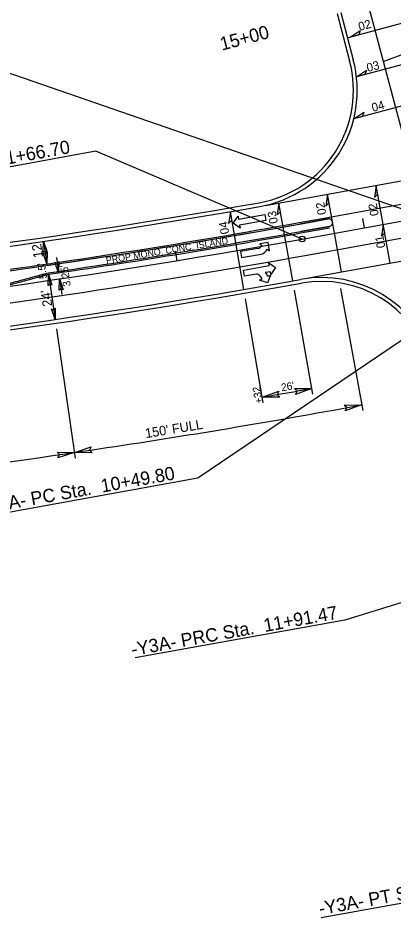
# Model space of a CAD drawing. Extents: x 1616561 to 1622460, y 896726 to 899651.
# Drawn here: x 1620740.5 to 1620937.7, y 897748.5 to 898221.3 of the extents above; entities that cross this region are included whole.
import ezdxf

# ---------------------------------------------------------------- set-up
doc = ezdxf.new("R2010")
doc.units = 0
for name, color, linetype in [('Exist Boundary Study Area', 7, 'Continuous'), ('Old_Level_3', 7, 'Continuous'), ('Prop Dimension', 7, 'Continuous'), ('Prop Horizontal Alignment Tick Small', 7, 'Continuous'), ('Prop Lane Arrow CELL', 7, 'Continuous'), ('Prop North Arrow NAD83 for Plan Sheets CELL', 7, 'Continuous'), ('Prop Shade Medium', 7, 'Continuous'), ('Prop Superelevation  Arrow CELL', 7, 'Continuous'), ('Prop Terminator CELL', 7, 'Continuous'), ('Sheet Cutting Line CELL', 7, 'Continuous'), ('Sheet North Arrow CELL', 7, 'Continuous'), ('Sheet Sticker Preliminary CELL', 7, 'Continuous')]:
    doc.layers.add(name, color=color, linetype=linetype)

msp = doc.modelspace()

# ---------------------------------------------------------------- linework, layer by layer
at = {"layer": 'Exist Boundary Study Area'}
for p, q in [((1620888.43, 898113.07), (1620903.49, 898115.8)), ((1620904.21, 898111.86), (1620889.15, 898109.14))]:
    msp.add_line(p, q, dxfattribs=at)
for centre, radius, start, end in [((1620903.85, 898113.83), 2, 280.2599, 100.2599), ((1620177.4, 902041.24), 3992, 277.72898, 280.25995), ((1620177.4, 902041.24), 3992, 278.41537, 280.25995), ((1620177.4, 902041.24), 3996, 278.33058, 280.25995), ((1620177.4, 902041.24), 3992, 278.33302, 278.41537)]:
    msp.add_arc(centre, radius, start, end, dxfattribs=at)
msp.add_open_spline([(1620715.49, 898076.55), (1620716.92, 898076.93), (1620722.41, 898078.36), (1620731.96, 898080.87), (1620742.09, 898083.56), (1620749.18, 898085.47), (1620752.22, 898086.29), (1620753.74, 898086.7), (1620754.25, 898086.84), (1620755.26, 898087.11), (1620755.77, 898087.25), (1620756.36, 898087.4)], degree=3, dxfattribs=at)
at = {"layer": 'Old_Level_3'}
for p, q in [((1620903.36, 898116.54), (1621261.54, 898181.37)), ((1620870.63, 898122.84), (1621020.48, 898149.94)), ((1620891.42, 898096.59), (1621018.65, 898119.62)), ((1620888.3, 898113.81), (1620903.36, 898116.54)), ((1620889.28, 898108.4), (1620904.34, 898111.13)), ((1620893.24, 898084.73), (1621042.18, 898111.69))]:
    msp.add_line(p, q, dxfattribs=at)
for radius, start in [(3991.25, 277.72898), (3996.75, 278.33058), (4008.75, 276.89819)]:
    msp.add_arc((1620177.4, 902041.24), radius, start, 280.25995, dxfattribs=at)
msp.add_open_spline([(1620715.59, 898075.81), (1620722.49, 898077.6), (1620729.29, 898079.39), (1620739.49, 898082.09), (1620742.88, 898083), (1620747.13, 898084.14), (1620747.98, 898084.37), (1620749.68, 898084.83), (1620750.53, 898085.06), (1620751.8, 898085.4), (1620752.44, 898085.57), (1620753.07, 898085.74), (1620753.5, 898085.86), (1620753.71, 898085.91), (1620754.35, 898086.09), (1620754.77, 898086.2), (1620755.62, 898086.43), (1620756.04, 898086.55), (1620756.47, 898086.66)], degree=3, dxfattribs=at)
at = {"layer": 'Prop Dimension'}
for p, q in [((1620753.93, 898103.98), (1620755.67, 898092.1)), ((1620760.65, 898095.41), (1620761.81, 898087.45)), ((1620756.47, 898086.66), (1620759.94, 898062.92)), ((1620762.28, 898084.23), (1620763.48, 898076.07)), ((1620910.11, 898079.25), (1620921.73, 898015.08)), ((1620910.11, 898079.25), (1620915.82, 898047.69)), ((1620760.67, 898057.97), (1620770.61, 897990.09)), ((1620906.32, 898015.34), (1620921.19, 898018.03))]:
    msp.add_line(p, q, dxfattribs=at)
for start, end in [(278.33169, 280.25995), (276.90211, 278.33169)]:
    msp.add_arc((1620176.16, 902049.2), 4099.41, start, end, dxfattribs=at)
at = {"layer": 'Prop Horizontal Alignment Tick Small'}
msp.add_line((1620908.26, 898223.61), (1620914.86, 898198.77), dxfattribs=at)
for centre, radius, start, end in [((1620856.87, 898183.37), 60, 279.9888, 14.8727), ((1620177.4, 902041.24), 3977.25, 270, 279.98877), ((1620177.4, 902041.24), 4022.75, 270, 280.19565), ((1620900.09, 898022.96), 60, 17.4099, 100.1956)]:
    msp.add_arc(centre, radius, start, end, dxfattribs=at)
at = {"layer": 'Prop Lane Arrow CELL'}
for p, q in [((1620853.63, 898113.48), (1620856.18, 898117.18)), ((1620856.18, 898117.18), (1620856.44, 898115.7)), ((1620856.44, 898115.7), (1620870.22, 898118.12)), ((1620870.79, 898114.87), (1620857.01, 898112.45)), ((1620870.22, 898118.12), (1620870.79, 898114.87)), ((1620857.27, 898110.98), (1620853.63, 898113.48)), ((1620857.01, 898112.45), (1620857.27, 898110.98)), ((1620872.03, 898103.34), (1620867.59, 898102.64)), ((1620867.59, 898102.64), (1620868.8, 898101.78)), ((1620872.72, 898099), (1620872.03, 898103.34)), ((1620866.53, 898100.22), (1620857.51, 898098.68)), ((1620857.51, 898098.68), (1620858.06, 898095.43)), ((1620858.06, 898095.43), (1620868.46, 898097.21)), ((1620871.51, 898099.86), (1620872.72, 898099)), ((1620859.03, 898088.87), (1620872.62, 898091.26)), ((1620872.62, 898091.26), (1620872.36, 898092.74)), ((1620872.36, 898092.74), (1620875.96, 898090.17)), ((1620859.6, 898085.62), (1620859.03, 898088.87)), ((1620865.95, 898086.74), (1620859.6, 898085.62)), ((1620873.19, 898088.01), (1620870.38, 898087.52)), ((1620873.19, 898086.28), (1620871.69, 898082.11)), ((1620871.83, 898085.64), (1620873.19, 898086.28)), ((1620873.45, 898086.53), (1620873.19, 898088.01)), ((1620875.96, 898090.17), (1620873.45, 898086.53)), ((1620867.52, 898083.61), (1620868.83, 898084.25)), ((1620871.69, 898082.11), (1620867.52, 898083.61))]:
    msp.add_line(p, q, dxfattribs=at)
for centre, radius, start, end in [((1620865.99, 898103.44), 3.27, 279.6782, 329.3364), ((1620866.81, 898102.17), 5.25, 288.3543, 333.666), ((1620865.74, 898084.22), 2.52, 49.0321, 85.3441), ((1620867.7, 898084), 4.43, 21.5498, 52.4284), ((1620864.7, 898082.61), 4.43, 21.6686, 52.5222)]:
    msp.add_arc(centre, radius, start, end, dxfattribs=at)
at = {"layer": 'Prop North Arrow NAD83 for Plan Sheets CELL'}
for points in [[(1620915.16, 898211.25), (1620920.45, 898214.72), (1620919.63, 898212.44)], [(1620918.47, 898190.4), (1620923.75, 898193.87), (1620922.94, 898191.59)], [(1620917.01, 898168.28), (1620922.29, 898171.76), (1620921.48, 898169.47)], [(1620928.78, 898133.33), (1620927.88, 898127.07), (1620929.6, 898128.78)], [(1620877.65, 898124.09), (1620876.74, 898117.83), (1620878.46, 898119.54)], [(1620903.19, 898128.7), (1620902.29, 898122.44), (1620904.01, 898124.15)], [(1620852.17, 898119.62), (1620851.22, 898113.37), (1620852.96, 898115.06)], [(1620932.47, 898112.91), (1620931.57, 898106.65), (1620933.29, 898108.36)]]:
    msp.add_lwpolyline(points, close=True, dxfattribs=at)
at = {"layer": 'Prop Shade Medium'}
for p, q in [((1620903.49, 898115.8), (1620888.43, 898113.07)), ((1620889.15, 898109.14), (1620904.21, 898111.86))]:
    msp.add_line(p, q, dxfattribs=at)
for centre, radius, start, end in [((1620903.85, 898113.83), 2, 280.2599, 100.2599), ((1620177.4, 902041.24), 3992, 277.72898, 280.25995), ((1620177.4, 902041.24), 3996, 278.33058, 280.25995)]:
    msp.add_arc(centre, radius, start, end, dxfattribs=at)
msp.add_open_spline([(1620715.49, 898076.55), (1620716.92, 898076.93), (1620722.41, 898078.36), (1620731.96, 898080.87), (1620742.09, 898083.56), (1620749.18, 898085.47), (1620752.22, 898086.29), (1620753.74, 898086.7), (1620754.25, 898086.84), (1620755.26, 898087.11), (1620755.77, 898087.25), (1620756.36, 898087.4)], degree=3, dxfattribs=at)
at = {"layer": 'Prop Superelevation  Arrow CELL'}
for p, q in [((1620922.63, 898111.13), (1620921.74, 898116.05)), ((1620824.13, 898093.87), (1620823.33, 898098.8))]:
    msp.add_line(p, q, dxfattribs=at)
at = {"layer": 'Prop Terminator CELL'}
for p in [(1620910.19, 898224.13), (1620916.61, 898199.96)]:
    msp.add_line(p, (1620916.79, 898199.28), dxfattribs=at)
for points in [[(1620753.78, 898098.04), (1620753.93, 898103.98), (1620755.81, 898098.31), (1620754.68, 898098.9)], [(1620755.82, 898098.04), (1620755.67, 898092.1), (1620753.79, 898097.77), (1620754.93, 898097.18)], [(1620761.96, 898093.38), (1620761.81, 898087.45), (1620759.93, 898093.12), (1620761.07, 898092.53)], [(1620756.32, 898080.73), (1620756.47, 898086.66), (1620758.35, 898080.99), (1620757.21, 898081.58)], [(1620762.13, 898078.3), (1620762.28, 898084.23), (1620764.16, 898078.56), (1620763.03, 898079.15)], [(1620760.09, 898068.85), (1620759.94, 898062.92), (1620758.06, 898068.58), (1620759.2, 898068)], [(1620878.08, 898022.12), (1620868.95, 898022.12), (1620877.6, 898025.23), (1620876.73, 898023.46)], [(1620885.93, 898026.64), (1620895.06, 898026.7), (1620886.43, 898023.53), (1620887.28, 898025.31)], [(1620912.06, 898017.95), (1620921.19, 898018.03), (1620912.57, 898014.85), (1620913.42, 898016.62)], [(1620761.04, 897993.28), (1620770.17, 897993.06), (1620761.45, 897990.16), (1620762.36, 897991.91)], [(1620779.3, 897992.83), (1620770.17, 897993.06), (1620778.9, 897995.95), (1620777.99, 897994.2)]]:
    msp.add_lwpolyline(points, close=True, dxfattribs=at)
for centre, radius, start, end in [((1620856.87, 898183.37), 62, 279.9888, 14.8727), ((1620177.4, 902041.24), 3979.25, 270, 279.98877), ((1620177.4, 902041.24), 4020.75, 270, 280.19565), ((1620900.09, 898022.96), 62, 17.4099, 100.1956)]:
    msp.add_arc(centre, radius, start, end, dxfattribs=at)
at = {"layer": 'Sheet Cutting Line CELL'}
for p, q in [((1620903.06, 898309.43), (1620954.2, 898116.85)), ((1620932.52, 898198.49), (1621073, 898251.08)), ((1620889.86, 898105.2), (1621477.45, 898211.56))]:
    msp.add_line(p, q, dxfattribs=at)
msp.add_arc((1620177.4, 902041.24), 4000, 270, 280.25995, dxfattribs=at)
at = {"layer": 'Sheet North Arrow CELL'}
for p, q in [((1620954.2, 898116.85), (1620693.65, 898206.85)), ((1620781.47, 898151.37), (1620681.08, 898133.2)), ((1620889.86, 898105.2), (1620781.47, 898151.37)), ((1620966.99, 898068.72), (1620834.98, 897979.47)), ((1620834.98, 897979.47), (1620722.68, 897959.15)), ((1621021.01, 897938.2), (1620912.28, 897905.02)), ((1620912.28, 897905.02), (1620802.13, 897885.09)), ((1621015.37, 897769.37), (1620899.93, 897748.48))]:
    msp.add_line(p, q, dxfattribs=at)
msp.add_circle((1620889.86, 898105.2), 1.5, dxfattribs=at)
at = {"layer": 'Sheet Sticker Preliminary CELL'}
for p, q in [((1620942.71, 898218.57), (1620914.12, 898210.98)), ((1620948.1, 898198.27), (1620918.47, 898190.4)), ((1620955.94, 898178.63), (1620917.01, 898168.28)), ((1620932.47, 898112.91), (1620928.78, 898133.33)), ((1620884.95, 898083.24), (1620877.65, 898124.09)), ((1620910.58, 898087.87), (1620903.19, 898128.7)), ((1620859.21, 898078.72), (1620852.17, 898119.62)), ((1620936.17, 898092.5), (1620932.47, 898112.91)), ((1620895.59, 898023.75), (1620885.83, 898078.31)), ((1620869.46, 898019.17), (1620860.06, 898073.79))]:
    msp.add_line(p, q, dxfattribs=at)
msp.add_arc((1620177.4, 902041.24), 4078.18, 279.76298, 280.1354, dxfattribs=at)

# ---------------------------------------------------------------- texts
at = {"layer": 'Prop Dimension'}
for s, height, rotation, p in [('15+00', 7, 14.8727, (1620847.71, 898204.14)), ('PROP MONO. CONC. ISLAND', 3.5, 9.3082, (1620787.02, 898092.19)), ("12'", 5, 98.3306, (1620753.68, 898095.65)), ("5.5'", 4, 98.3306, (1620755.8, 898084.55)), ("3.25'", 4, 98.3306, (1620768.21, 898080.51)), ("24'", 5, 98.3306, (1620758.51, 898070.08)), ("150' FULL", 5, 9.2431, (1620807.75, 898000.58))]:
    msp.add_text(s, height=height, rotation=rotation, dxfattribs=at).set_placement(p)
at = {"layer": 'Sheet North Arrow CELL'}
for s, p in [('-L- PT Sta.  41+66.70', (1620679.92, 898134.37)), ('-Y3A- PC Sta.  10+49.80', (1620721.72, 897960.55)), ('-Y3A- PRC Sta.  11+91.47', (1620800.67, 897886.1)), ('-Y3A- PT Sta.  13+28.20', (1620899.33, 897749.95))]:
    msp.add_text(s, height=7, rotation=10.2599, dxfattribs=at).set_placement(p)
at = {"layer": 'Sheet Sticker Preliminary CELL'}
for s, height, rotation, p in [('02', 4.5, 14.8727, (1620920.12, 898214.52)), ('03', 4.5, 14.8727, (1620924.45, 898192.88)), ('04', 4.5, 14.8727, (1620927.1, 898171.96)), ('02', 4.5, 100.2599, (1620902.59, 898118.32)), ('02', 4.5, 100.2599, (1620930.23, 898117.75)), ('03', 4.5, 100.1397, (1620877.19, 898113.67)), ('04', 4.5, 99.7672, (1620851.57, 898108.12)), ('01', 4.5, 100.2599, (1620933.71, 898100.83)), ("26'", 4, 9.8833, (1620879.17, 898025.16)), ('+32', 4, 99.5179, (1620869.19, 898019.03))]:
    msp.add_text(s, height=height, rotation=rotation, dxfattribs=at).set_placement(p)

doc.saveas('drawing.dxf')
